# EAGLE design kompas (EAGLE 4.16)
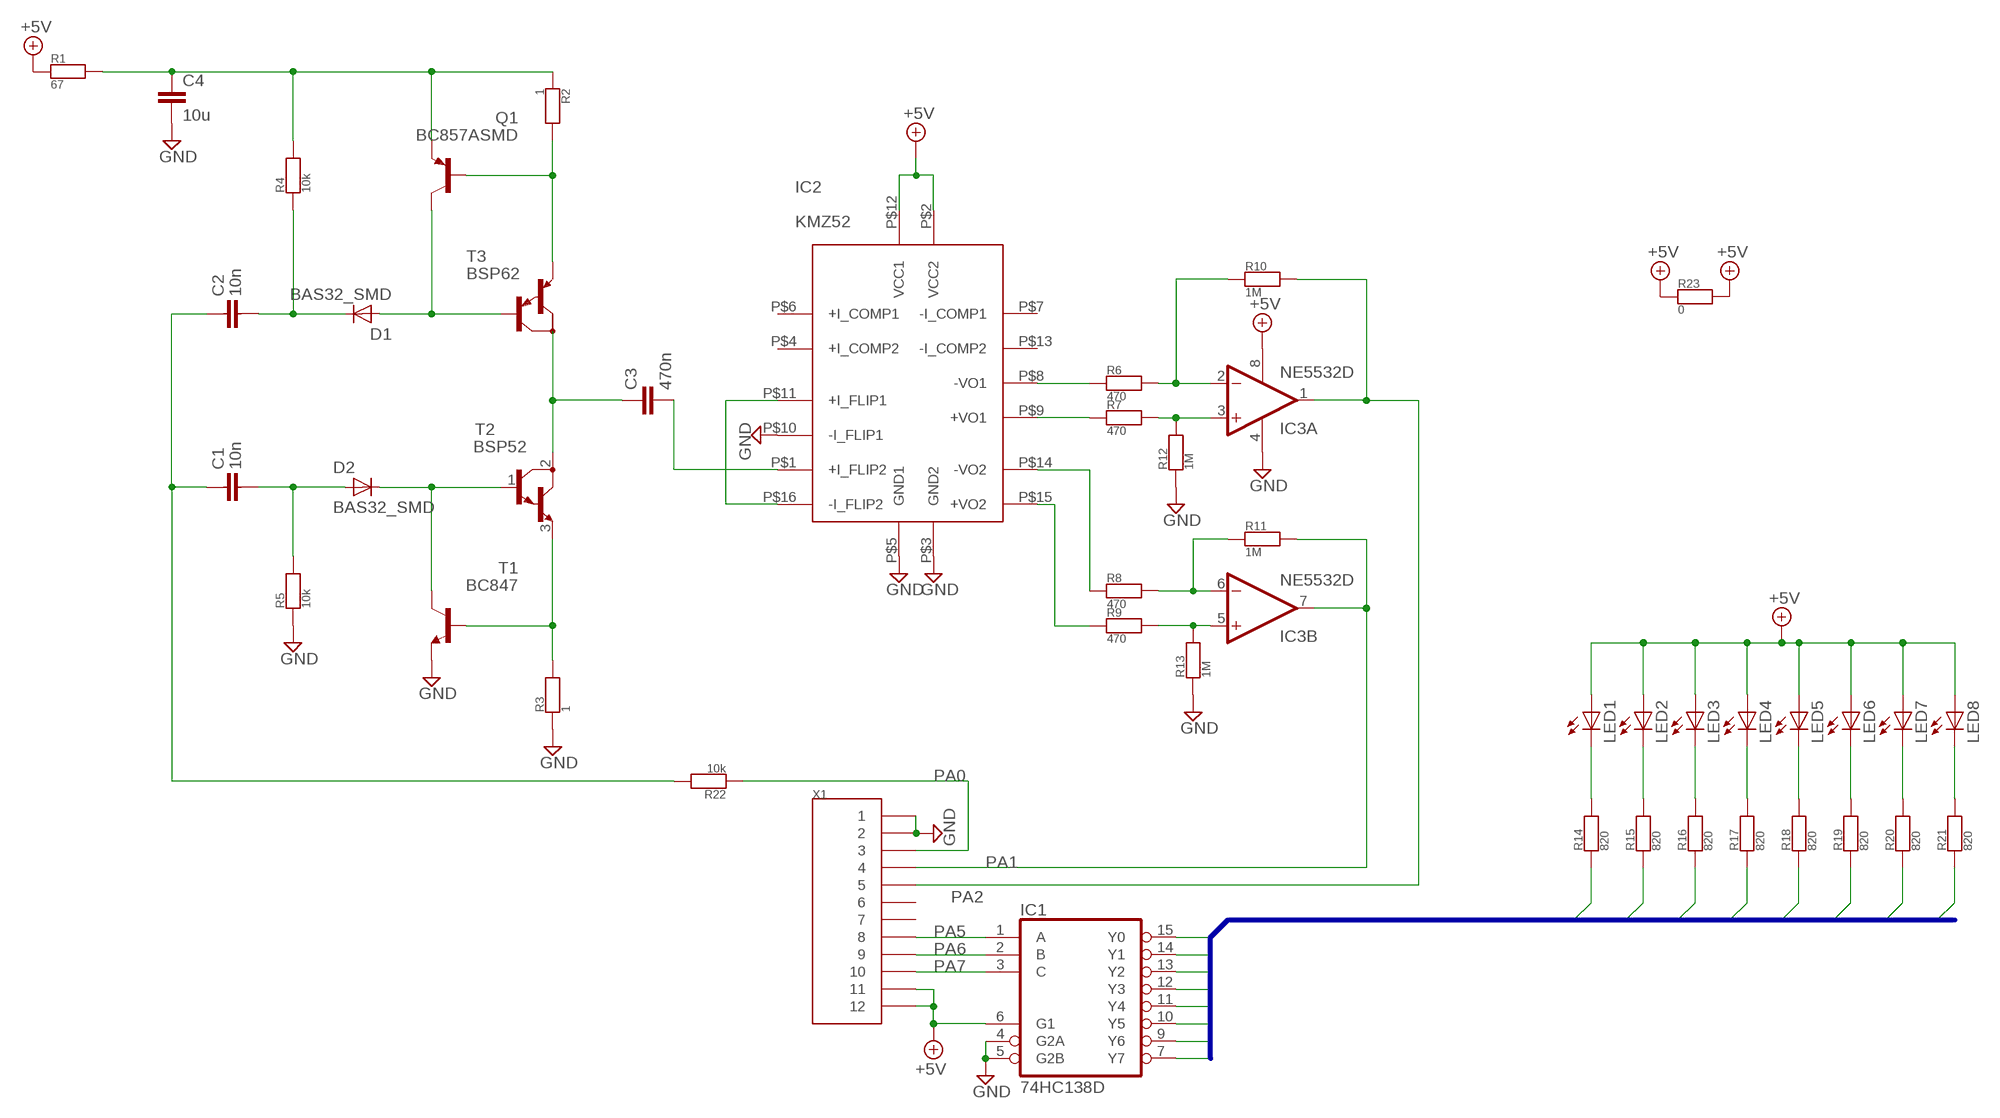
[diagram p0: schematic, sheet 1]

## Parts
C1  10n  C0805_0.6  [0805_DRAT_0.6]
C2  10n  C0805_0.6  [0805_DRAT_0.6]
C3  470n  C-EUC1210  [C1210]
C4  10u  C-EUC1210  [C1210]
D1  BAS32_SMD  [SOD80]
D2  BAS32_SMD  [SOD80]
IC1  74HC138D  [SO16]
IC2  KMZ52  [SO16_REDUKCE]
IC3  NE5532D  [SO08]
LED1  LEDCHIP-LED0805  [CHIP-LED0805]
LED2  LEDCHIP-LED0805  [CHIP-LED0805]
LED3  LEDCHIP-LED0805  [CHIP-LED0805]
LED4  LEDCHIP-LED0805  [CHIP-LED0805]
LED5  LEDCHIP-LED0805  [CHIP-LED0805]
LED6  LEDCHIP-LED0805  [CHIP-LED0805]
LED7  LEDCHIP-LED0805  [CHIP-LED0805]
LED8  LEDCHIP-LED0805  [CHIP-LED0805]
Q1  BC857ASMD  [SOT23-BEC]
R1  67  R0805_0.6  [0805_DRAT_0.6]
R2  1  R0805_0.6  [0805_DRAT_0.6]
R3  1  R0805_0.6  [0805_DRAT_0.6]
R4  10k  R0805_0.6  [0805_DRAT_0.6]
R5  10k  R0805_0.6  [0805_DRAT_0.6]
R6  470  R0805_0.6  [0805_DRAT_0.6]
R7  470  R0805_0.6  [0805_DRAT_0.6]
R8  470  R0805_0.6  [0805_DRAT_0.6]
R9  470  R0805_0.6  [0805_DRAT_0.6]
R10  1M  R0805_0.6  [0805_DRAT_0.6]
R11  1M  R0805_0.6  [0805_DRAT_0.6]
R12  1M  R0805_0.6  [0805_DRAT_0.6]
R13  1M  R0805_0.6  [0805_DRAT_0.6]
R14  820  R0805_0.6  [0805_DRAT_0.6]
R15  820  R0805_0.6  [0805_DRAT_0.6]
R16  820  R0805_0.6  [0805_DRAT_0.6]
R17  820  R0805_0.6  [0805_DRAT_0.6]
R18  820  R0805_0.6  [0805_DRAT_0.6]
R19  820  R0805_0.6  [0805_DRAT_0.6]
R20  820  R0805_0.6  [0805_DRAT_0.6]
R21  820  R0805_0.6  [0805_DRAT_0.6]
R22  10k  R0805_0.6  [0805_DRAT_0.6]
R23  0  R0805_0.6  [0805_DRAT_0.6]
T1  BC847  [SOT23]
T2  BSP52  [SOT223]
T3  BSP62  [SOT223]
X1  CON12CON12  [CON12]

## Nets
+5V: IC1.6(G1) IC2.P$2(VCC2) IC2.P$12(VCC1) IC3.8(P:V+) LED1.A LED2.A LED3.A LED4.A LED5.A LED6.A LED7.A LED8.A R1.1 R23.1 R23.2 X1.11 X1.12
GND: C4.2 IC1.4(G2A) IC1.5(G2B) IC2.P$3(GND2) IC2.P$5(GND1) IC2.P$10(-I_FLIP1) IC3.4(P:V-) R3.1 R5.1 R12.1 R13.1 T1.2(E) X1.1 X1.2
N$1: C3.2 IC2.P$1(+I_FLIP2)
N$2: IC2.P$11(+I_FLIP1) IC2.P$16(-I_FLIP2)
N$3: C3.1 T2.2(C) T3.2(C)
N$4: R3.2 T1.1(B) T2.3(E)
N$5: D2.A T1.3(C) T2.1(B)
N$6: C1.2 D2.K R5.2
N$7: C2.2 D1.A R4.1
N$8: D1.K Q1.C T3.1(B)
N$9: Q1.B R2.2 T3.3(E)
N$10: C4.1 Q1.E R1.2 R2.1 R4.2
N$11: C1.1 C2.1 R22.2
N$12: IC2.P$8(-VO1) R6.1
N$13: IC3.2(A:-IN) R6.2 R10.1
N$14: IC3.1(A:OUT) R10.2 X1.5
N$15: IC3.3(A:+IN) R7.2 R12.2
N$16: IC2.P$9(+VO1) R7.1
N$17: IC2.P$14(-VO2) R8.1
N$18: IC3.6(B:-IN) R8.2 R11.1
N$19: IC3.7(B:OUT) R11.2 X1.4
N$20: IC3.5(B:+IN) R9.2 R13.2
N$21: IC2.P$15(+VO2) R9.1
N$22: IC1.3(C) X1.10
N$23: IC1.2(B) X1.9
N$24: IC1.1(A) X1.8
N$25: LED1.C R14.2
N$26: LED2.C R15.2
N$27: LED3.C R16.2
N$28: LED4.C R17.2
N$29: LED5.C R18.2
N$30: LED6.C R19.2
N$31: LED7.C R20.2
N$32: LED8.C R21.2
N$33: R22.1 X1.3
Y0: IC1.15(Y0) R14.1
Y1: IC1.14(Y1) R15.1
Y2: IC1.13(Y2) R16.1
Y3: IC1.12(Y3) R17.1
Y4: IC1.11(Y4) R18.1
Y5: IC1.10(Y5) R19.1
Y6: IC1.9(Y6) R20.1
Y7: IC1.7(Y7) R21.1
Unconnected: IC2.P$4(+I_COMP2) IC2.P$6(+I_COMP1) IC2.P$7(-I_COMP1) IC2.P$13(-I_COMP2) T2.4(C) T3.4(C) X1.6 X1.7

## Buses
B$1

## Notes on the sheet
- PA0
- PA1
- PA2
- PA5
- PA6
- PA7

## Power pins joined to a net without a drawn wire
GND: IC1.8(GND)
VCC: IC1.16(VCC)

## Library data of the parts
C1 C2 = moje:C
C3 C4 = rcl:C-EU: CAPACITOR, European symbol
D1 D2 = moje:BAS32_SMD
IC1 = 74xx-eu:74*138: 3-line to 8-line DECODER/DEMULTIPLEXER
IC2 = moje:KMZ52
IC3 = linear:NE5532: AUDIO AMPLIFIER
LED1-LED8 = led:LED: LED
Q1 = transistor-pnp:BC857*: PNP Transistror
R1-R23 = moje:R
T1 = transistor:BC847: NPN TRANSISTOR
T2 = moje:BSP52
T3 = moje:BSP62
X1 = moje:CON12

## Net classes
0 default: width 0.4 mm

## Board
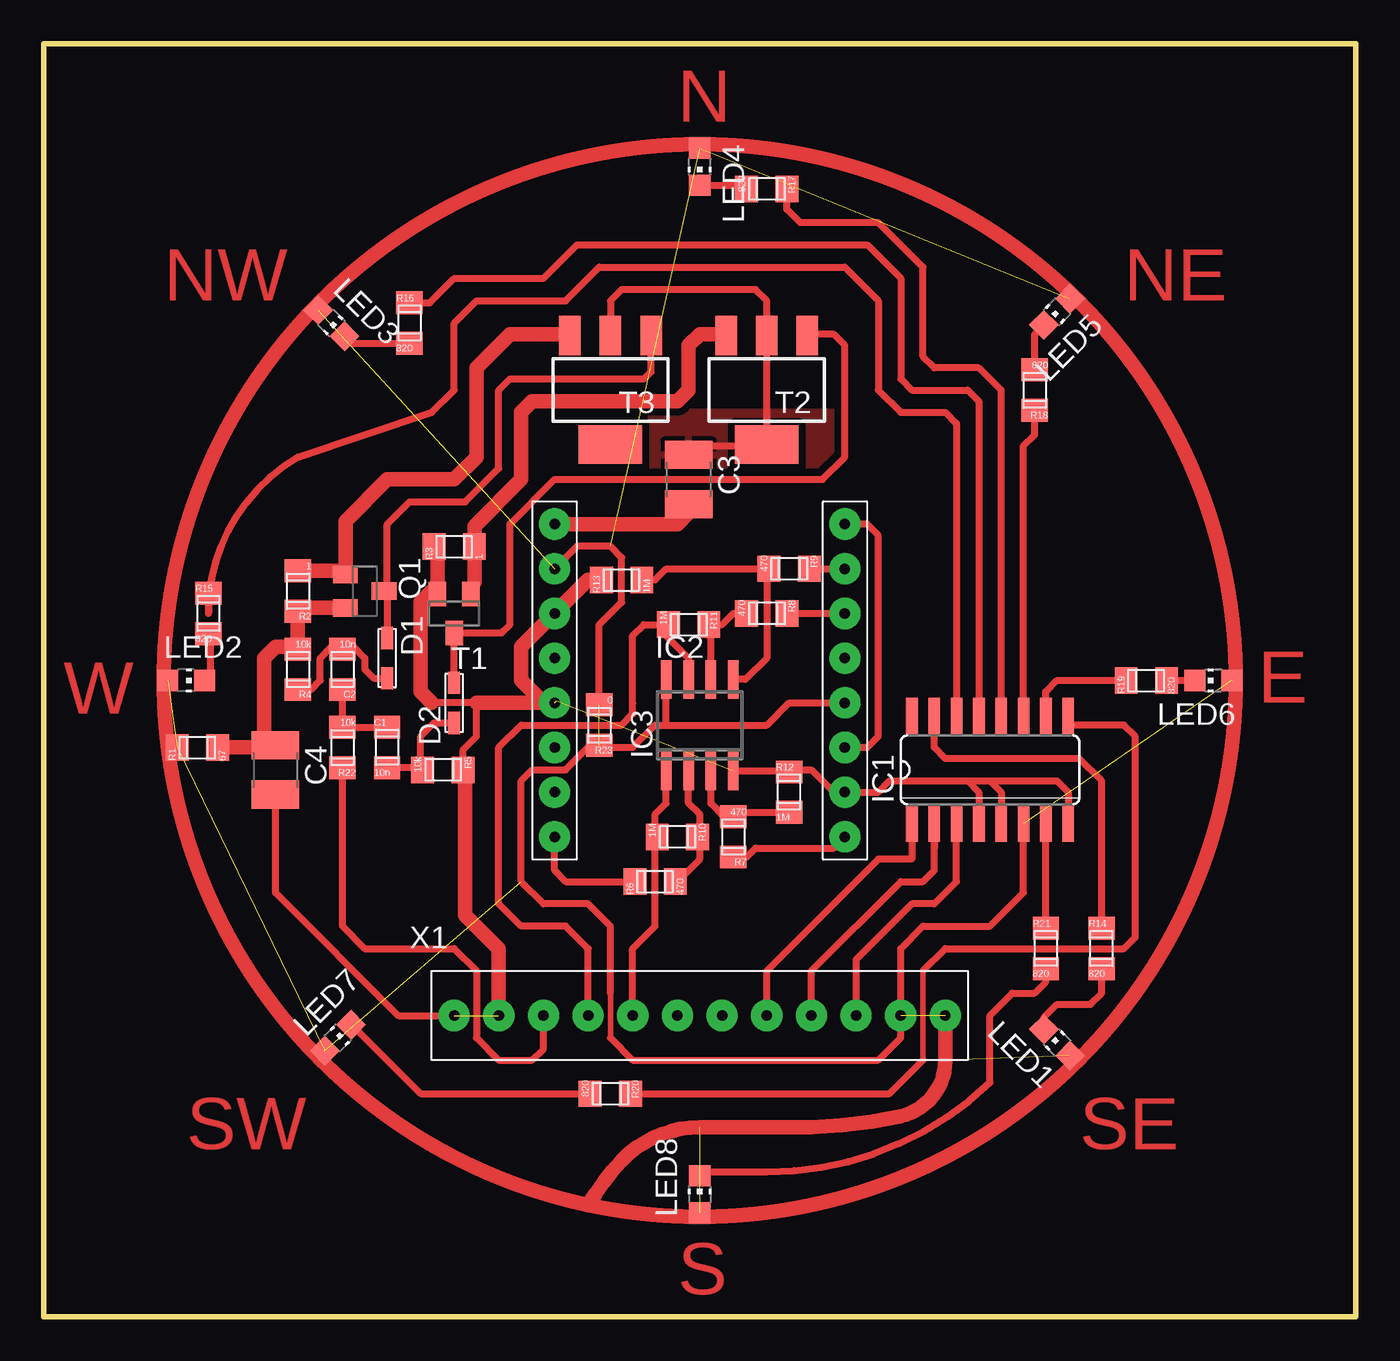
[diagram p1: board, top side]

Size 74.6 x 72.38 mm. Coordinates in mm from the lower left corner, seen from the top.
Outline: 0,0 74.6,0 74.6,72.38 0,72.38 0,0
Copper layers (1*16): Top 0.035mm / dielectric 1.5mm / Bottom 0.035mm
Design rules "default": minimum track width 10mil, minimum drill 24mil, track to track 8mil, track to pad 8mil, pad to pad 8mil, via to via 8mil, smd to smd 8mil, copper to edge 40mil, drill to drill 8mil, minimum pad ring 10mil, minimum via ring 8mil, stop-mask expansion 4mil, vias tented up to drill 0mil, thermal gap 10mil

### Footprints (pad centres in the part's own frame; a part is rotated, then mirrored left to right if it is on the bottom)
0805_DRAT_0.6 = smd 1.3 x 1.5: 1 -1.15,0; 2 1.15,0
C1210 = smd 1.6 x 2.7: 1 -1.4,0; 2 1.4,0
SOD80 = smd 1.27 x 0.66: A 1.143,0; K -1.143,0
SO16 = smd 0.66 x 2.032: 1 -4.445,-3.073; 2 -3.175,-3.073; 3 -1.905,-3.073; 4 -0.635,-3.073; 5 0.635,-3.073; 6 1.905,-3.073; 7 3.175,-3.073; 8 4.445,-3.073; 9 4.445,3.073; 10 3.175,3.073; 11 1.905,3.073; 12 0.635,3.073; 13 -0.635,3.073; 14 -1.905,3.073; 15 -3.175,3.073; 16 -4.445,3.073
SO16_REDUKCE = drill 0.6 pad 1.778 round: P$1 -8.255,8.89; P$2 -8.255,6.35; P$3 -8.255,3.81; P$4 -8.255,1.27; P$5 -8.255,-1.27; P$6 -8.255,-3.81; P$7 -8.255,-6.35; P$8 -8.255,-8.89; P$9 8.255,-8.89; P$10 8.255,-6.35; P$11 8.255,-3.81; P$12 8.255,-1.27; P$13 8.255,1.27; P$14 8.255,3.81; P$15 8.255,6.35; P$16 8.255,8.89
SO08 = smd 0.6 x 2.2: 1 -1.905,-2.6; 2 -0.635,-2.6; 3 0.635,-2.6; 4 1.905,-2.6; 5 1.905,2.6; 6 0.635,2.6; 7 -0.635,2.6; 8 -1.905,2.6
CHIP-LED0805 = smd 1.2 x 1.2: A 0,-1.05; C 0,1.05
SOT23-BEC = smd 1 x 1.4: B -0.95,-1.1; C 0,1.1; E 0.95,-1.1
SOT23 = smd 1 x 1.4: 1 -0.95,-1.1; 2 0.95,-1.1; 3 0,1.1
SOT223 = smd 1.219 x 2.235: 1 -2.311,-3.099; 2 0,-3.099; 3 2.311,-3.099 | smd 3.6 x 2.2: 4 0,3.099
CON12 = drill 0.6 pad 1.778 round: 1 0,0; 2 2.54,0; 3 5.08,0; 4 7.62,0; 5 10.16,0; 6 12.7,0; 7 15.24,0; 8 17.78,0; 9 20.32,0; 10 22.86,0; 11 25.4,0; 12 27.94,0

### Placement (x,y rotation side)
C1  19.52,32.38 270 top
C2  16.98,36.83 90 top
C3  36.66,47.62 270 top
C4  13.17,31.11 270 top
D1  19.52,37.46 270 top
D2  23.33,34.92 90 top
IC1  53.81,31.11 0 top
IC2  37.3,36.19 0 top
IC3  37.3,33.65 0 top
LED1  57.62,15.61 45 top
LED2  8.09,36.19 270 top
LED3  16.34,56.51 225 top
LED4  37.3,65.4 180 top
LED5  57.62,57.15 135 top
LED6  66.51,36.19 90 top
LED7  16.72,15.87 315 top
LED8  37.3,6.98 0 top
Q1  18.25,41.27 270 top
R1  8.73,32.38 0 top
R2  14.44,41.27 90 top
R3  23.33,43.81 0 top
R4  14.44,36.83 90 top
R5  22.7,31.11 180 top
R6  34.76,24.76 0 top
R7  39.2,27.3 90 top
R8  41.11,40 180 top
R9  42.38,42.54 180 top
R10  36.03,27.3 180 top
R11  36.66,39.37 180 top
R12  42.38,29.84 270 top
R13  32.85,41.91 0 top
R14  60.16,20.95 270 top
R15  9.36,40 270 top
R16  20.79,56.51 270 top
R17  41.11,64.13 180 top
R18  56.35,52.7 90 top
R19  62.7,36.19 0 top
R20  32.22,12.7 180 top
R21  56.98,20.95 270 top
R22  16.98,32.38 90 top
R23  31.59,33.65 90 top
T1  23.33,40 180 top
T2  41.11,52.7 180 top
T3  32.22,52.7 180 top
X1  23.33,17.14 0 top

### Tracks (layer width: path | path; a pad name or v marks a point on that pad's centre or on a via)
+5V  (11 unrouted)
  Top 0.305: 32.22,15.87 32.22,18.41
  Top 0.406: LED1.A 58.36,14.71 | 32.22,15.87 33.49,14.6 47.46,14.6 48.73,15.87 X1.11 48.73,20.95 50,22.22 53.81,22.22 55.72,24.12 IC1.6 | 30.95,32.38 29.68,31.11 27.77,31.11 27.14,30.48 27.14,24.76 28.41,23.49 30.95,23.49 32.22,22.22 32.22,18.41 | 30.95,32.38 33.49,32.38 34.76,33.65 35.4,33.65 | 30.95,32.38 R23.1 | R23.2 31.59,39.37 32.85,40.63 32.85,43.17 32.22,43.81 30.31,43.81 IC2.P$2 | 35.4,33.65 IC3.8 | 35.4,33.65 41.11,33.65 42.38,34.92 IC2.P$12
  Top 0.813: X1.12 51.27,14.6 arc-77 48.73,11.43 arc-11 43.65,10.79 37.3,10.79 arc46 32.85,8.88 arc13 30.95,6.35
GND  (3 unrouted)
  Top 0.406: 39.2,30.48 IC3.4 42.32,31.05 42.38,31.11 | R3.1 22.06,43.81 22.38,43.49 | 52.54,30.48 53.17,30.48 | 53.17,30.48 53.81,30.48 54.44,29.84 IC1.5 54.44,27.93 | IC1.4 53.17,29.84 52.54,30.48 | IC1.8 58.25,29.84 57.62,30.48 53.17,30.48 | 22.06,41.27 22.23,41.1 T1.2 | 22.06,34.92 24.6,34.92 24.6,33.02 23.84,32.26 R5.1 23.97,31.11 | 52.54,30.48 48.09,30.48 47.46,29.84 IC2.P$10 44.92,29.84 43.65,31.11 42.38,31.11 | 28.29,35.04 29.16,35.04 | C4.2 13.17,24.12 20.16,17.14 X1.1 | 42.38,31.11 R12.1
  Top 0.813: T1.2 22.38,43.49 | 22.06,34.92 21.42,35.55 21.42,40.63 22.06,41.27 | 24.6,34.92 IC2.P$5 | 28.29,35.04 27.14,36.19 27.14,38.09 IC2.P$3 30.95,41.91 R13.1 | X1.2 25.87,20.95 23.97,22.86 23.97,31.11
N$1
  Top 0.813: C3.2 36.66,45.72 36.03,45.08 IC2.P$1
N$2
  Top 0.406: IC2.P$16 46.83,45.08 47.46,44.45 47.46,33.02 46.83,32.38 IC2.P$11
N$3
  Top 0.406: T3.2 32.22,57.78 32.85,58.41 40.48,58.41 41.11,57.78 T2.2 41.11,50.16 40.48,49.52 37.3,49.52 36.66,48.89 C3.1
  pour Top (isolate 0.406): 27.14,51.43 27.14,47.62 44.92,47.62 44.92,51.43
N$4
  Top 0.406: T1.1 24.13,41.1 23.97,41.27 24.48,41.79 | 38.57,55.88 38.65,55.8 T2.3
  Top 0.813: 24.48,41.79 R3.2 24.48,44.96 27.14,47.62 27.14,51.43 27.77,52.06 36.03,52.06 36.66,52.7 36.66,55.24 37.3,55.88 38.57,55.88
N$5
  Top 0.406: D2.A T1.3 26.04,38.9 26.51,39.37 26.51,45.08 29.05,47.62 44.28,47.62 45.55,48.89 45.55,55.24 44.92,55.88 43.65,55.88 43.57,55.8 T2.1
N$6
  Top 0.406: C1.2 21.3,31.23 21.42,31.11 | D2.K 22.19,33.78 21.42,33.02 21.42,31.11 | R5.2 21.42,31.11
N$7
  Top 0.406: D1.A 18.76,36.32 18.25,36.83 18.25,37.46 17.61,38.09 16.98,38.09 | R4.1 15.2,35.67 15.71,36.19 15.71,37.46 16.34,38.09 16.98,38.09 | 16.98,38.09 C2.2
N$8
  Top 0.406: Q1.C 19.52,41.27 | 19.52,41.27 D1.K | 19.52,41.27 19.52,45.08 20.79,46.35 23.97,46.35 25.87,48.26 25.87,52.7 26.51,53.34 34.12,53.34 34.53,53.74 T3.1
N$9
  Top 0.406: Q1.B 17.15,42.37 16.98,42.54 16.86,42.42 | 29.68,55.88 29.76,55.8 T3.3
  Top 0.813: R2.2 16.86,42.42 | 17.15,42.37 17.15,45.25 19.52,47.62 23.33,47.62 24.6,48.89 24.6,53.97 26.51,55.88 29.68,55.88
N$10
  Top 0.406: 14.76,40.32 14.44,40 R2.1 | 13.17,32.38 C4.1 13.04,32.51 12.54,33.02 | 14.44,38.09 R4.2
  Top 0.813: 14.76,40.32 Q1.E | 14.44,40 14.44,38.09 13.17,38.09 12.54,37.46 12.54,33.02 | R1.2 13.17,32.38
N$11
  Top 0.406: C1.1 17.1,33.53 16.98,33.65 R22.2 C2.1
N$12
  Top 0.406: IC2.P$8 29.05,25.39 29.68,24.76 R6.1
N$13
  Top 0.406: 36.66,31.11 IC3.2 36.66,29.2 37.3,28.57 37.3,27.3 | R6.2 36.03,24.76 37.3,26.03 37.3,27.3 | 37.3,27.3 R10.1
N$14
  Top 0.406: IC3.1 35.4,29.2 34.76,28.57 34.76,27.3 | X1.5 33.49,20.95 34.76,22.22 34.76,27.3 | 34.76,27.3 R10.2
N$15
  Top 0.406: R12.2 39.33,28.69 39.2,28.57 R7.2 38.69,28.45 37.94,29.2 IC3.3 37.94,31.11
N$16
  Top 0.406: R7.1 39.96,26.15 40.48,26.66 44.92,26.66 IC2.P$9
N$17
  Top 0.406: R8.1 IC2.P$14
N$18
  Top 0.406: IC3.6 37.94,39.37 R11.1 38.57,39.37 39.2,40 R8.2
N$19
  Top 0.406: X1.4 30.95,20.95 29.68,22.22 27.14,22.22 25.87,23.49 25.87,32.38 27.14,33.65 32.22,33.65 32.85,33.65 33.49,34.29 33.49,34.92 33.49,38.73 34.12,39.37 35.4,39.37 | IC3.7 36.66,37.46 35.4,38.73 35.4,39.37 | 35.4,39.37 R11.2
N$20
  Top 0.406: 39.2,36.19 IC3.5 39.9,36.25 41.11,37.46 41.11,41.91 41.23,42.02 R9.2 35.4,42.54 34.76,41.91 R13.2
N$21
  Top 0.406: R9.1 IC2.P$15
N$22
  Top 0.406: IC1.3 51.91,24.76 50.64,23.49 49.37,23.49 46.19,20.32 X1.10
N$23
  Top 0.406: 50.64,27.3 50.64,26.66 | 50.64,27.3 IC1.2 | 50.64,27.3 50.64,25.39 50,24.76 48.73,24.76 43.65,19.68 X1.9
N$24
  Top 0.406: X1.8 41.11,19.68 47.46,26.03 49.37,26.03 IC1.1
N$25
  Top 0.406: LED1.C 56.88,17.03 57.62,17.77 59.53,17.77 60.16,18.41 R14.2
N$26
  Top 0.406: LED2.C 9.36,36.19 9.48,36.31 9.48,38.61 9.36,38.73 R15.2
N$27
  Top 0.406: LED3.C 16.98,55.88 | LED3.C | R16.2 17.5,55.36 LED3.C
N$28
  Top 0.406: R17.2 39.84,64.13 39.62,64.35 LED4.C
N$29
  Top 0.406: 56.98,56.51 LED5.C 56.35,55.88 R18.2
N$30
  Top 0.406: R19.2 LED6.C
N$31
  Top 0.406: LED7.C 17.51,16.61 21.42,12.7 R20.2
N$32
  Top 0.406: LED8.C 37.3,8.25 41.11,8.25 arc44 53.81,13.33 53.81,17.14 55.08,18.41 56.35,18.41 56.98,19.05 R21.2
N$33
  Top 0.406: X1.3 28.41,15.23 27.77,14.6 25.87,14.6 24.6,15.87 24.6,19.68 23.33,20.95 18.25,20.95 16.98,22.22 R22.1
Y0
  Top 0.406: 50.64,34.29 IC1.15 50.64,32.38 51.27,31.74 58.89,31.74 60.16,30.48 R14.1
Y1
  Top 0.406: IC1.14 51.91,50.8 51.27,51.43 48.73,51.43 47.46,52.7 47.46,57.78 45.55,59.69 31.59,59.69 29.68,57.78 24.6,57.78 23.33,56.51 23.33,52.7 22.06,51.43 14.44,48.89 arc59 9.36,40 R15.1
Y2
  Top 0.406: R16.1 21.94,57.66 23.33,59.05 28.41,59.05 30.31,60.96 46.83,60.96 48.73,59.05 48.73,53.34 49.37,52.7 52.54,52.7 53.17,52.06 IC1.13
Y3
  Top 0.406: R17.1 42.26,62.98 43.02,62.23 47.46,62.23 50,59.69 50,54.6 50.64,53.97 53.17,53.97 54.44,52.7 IC1.12
Y4
  Top 0.406: IC1.11 55.72,49.52 56.35,50.16 R18.1
Y5
  Top 0.406: R19.1 57.62,36.19 56.98,35.55 IC1.10
Y6
  Top 0.305: 50,14.6 50,19.68
  Top 0.406: IC1.9 58.25,33.65 61.43,33.65 62.06,33.02 62.06,21.59 61.43,20.95 51.27,20.95 50,19.68 | R20.1 48.09,12.7 50,14.6
Y7
  Top 0.406: R21.1 IC1.7
(copper drawn outside any net)
  shapes: Top circle x1

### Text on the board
Top: N | NW | NE | E | W | SW | SE | S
